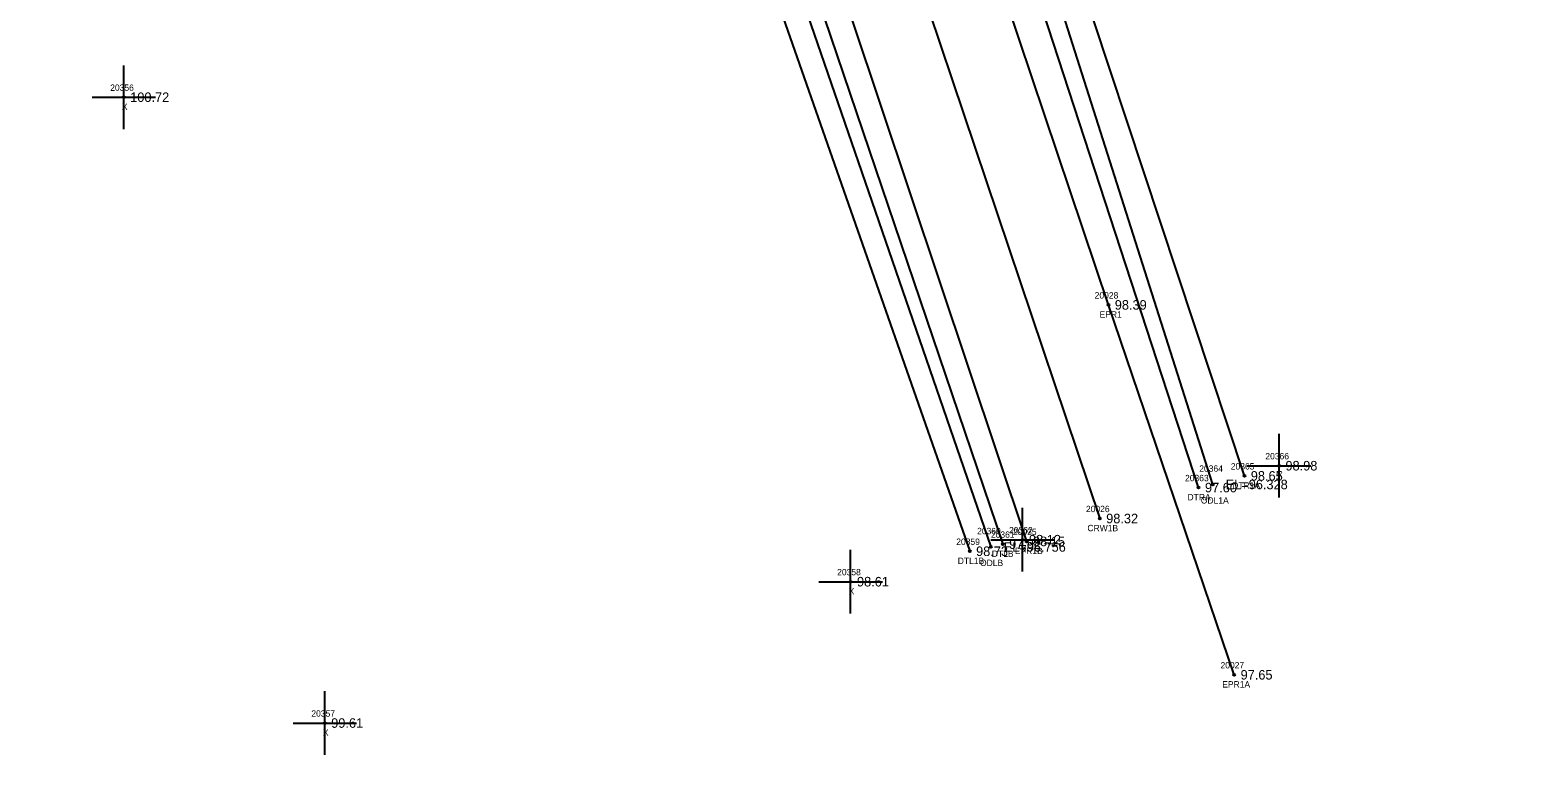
# Model space of a CAD drawing. Extents: x 2530197 to 2532051, y 935230 to 936631.
# Drawn here: x 2530401.9 to 2530638.9, y 935229.9 to 935343.8 of the extents above; entities that cross this region are included whole.
import ezdxf

# ---------------------------------------------------------------- set-up
doc = ezdxf.new("R2010")
doc.units = 0
for name, color, linetype in [('RD_DTM_BkLn1', 7, 'Continuous'), ('RD_EX_H2O', 7, 'Continuous'), ('RD_EX_H2O_txCode', 7, 'Continuous'), ('RD_EX_Misc', 7, 'Continuous'), ('RD_EX_Misc_txCode', 7, 'Continuous'), ('RD_EX_Road', 7, 'Continuous'), ('RD_EX_Road_txCode', 7, 'Continuous'), ('RD_EX_TX_H2O_ELEV', 7, 'Continuous'), ('RD_EX_TX_Misc_ELEV', 7, 'Continuous'), ('RD_EX_TX_Road_ELEV', 7, 'Continuous'), ('RD_HC_Survey_ELEV', 7, 'Continuous'), ('RD_HC_Survey_txCode', 7, 'Continuous'), ('RD_SMD_Locator', 7, 'Continuous')]:
    doc.layers.add(name, color=color, linetype=linetype)

msp = doc.modelspace()

# ---------------------------------------------------------------- linework, layer by layer
at = {"layer": 'RD_DTM_BkLn1'}
msp.add_lwpolyline([(2530465.37, 935579.66), (2530474.48, 935552.87), (2530506.43, 935456.79), (2530537.92, 935362.65), (2530570.08, 935267.03)], dxfattribs=at)
at = {"layer": 'RD_EX_H2O'}
for points in [[(2530585.61, 935271.89), (2530554.63, 935366.84), (2530523, 935462.44), (2530497.71, 935534.53), (2530497.63, 935550.35), (2530501.9, 935567.07), (2530512.76, 935580.06), (2530532.29, 935593.54), (2530580.75, 935621.41), (2530622.78, 935645.99), (2530706.38, 935694.8)], [(2530592.81, 935273.73), (2530561.2, 935369.39), (2530529.39, 935464.13), (2530504.24, 935535.46), (2530502.94, 935549.83), (2530506.75, 935563.82), (2530516.63, 935575.2), (2530535.16, 935588.8), (2530583.24, 935617.5), (2530624.86, 935641.7), (2530708.31, 935690.59), (2530708.33, 935693.17), (2530706.38, 935694.8)], [(2530587.86, 935272.38), (2530557.35, 935368.29), (2530525.38, 935463.03), (2530500.38, 935535.14), (2530499.61, 935550.4), (2530504.44, 935565.67), (2530514.36, 935577.87), (2530533.45, 935591.79), (2530582.01, 935619.78), (2530623.26, 935643.67), (2530705.7, 935692.18)], [(2530212.43, 935575.3), (2530312.61, 935575.57), (2530413.4, 935574.03), (2530431.14, 935570.94), (2530447.74, 935563.43), (2530459.72, 935547.88), (2530491.74, 935452.52), (2530522.77, 935357.57), (2530554.82, 935263)], [(2530212.28, 935572.05), (2530311.96, 935572.07), (2530413.48, 935570.72), (2530429.97, 935567.74), (2530445.97, 935560.86), (2530457.18, 935547.13), (2530489.52, 935451.8), (2530520.38, 935357.21), (2530552.97, 935262.56)], [(2530212.78, 935569.06), (2530311.54, 935568.98), (2530412.57, 935565.49), (2530428.32, 935562.93), (2530442.59, 935555.84), (2530453.4, 935544.85), (2530485.1, 935450.23), (2530516.56, 935356.42), (2530549.63, 935261.88)]]:
    msp.add_lwpolyline(points, dxfattribs=at)
at = {"layer": 'RD_EX_Misc'}
for p, q in [((2530416.66, 935328.26), (2530416.66, 935338.26)), ((2530411.66, 935333.26), (2530421.66, 935333.26)), ((2530598.26, 935270.33), (2530598.26, 935280.33)), ((2530593.26, 935275.33), (2530603.26, 935275.33)), ((2530557.95, 935258.7), (2530557.95, 935268.7)), ((2530552.95, 935263.7), (2530562.95, 935263.7)), ((2530530.91, 935252.1), (2530530.91, 935262.1)), ((2530525.91, 935257.1), (2530535.91, 935257.1)), ((2530448.26, 935229.88), (2530448.26, 935239.88)), ((2530443.26, 935234.88), (2530453.26, 935234.88))]:
    msp.add_line(p, q, dxfattribs=at)
at = {"layer": 'RD_EX_Road'}
for points in [[(2530591.21, 935242.46), (2530571.43, 935300.61), (2530549.4, 935366.29), (2530518.07, 935460.9), (2530493.7, 935533.55), (2530494.46, 935557.42), (2530501.12, 935573.63), (2530518.05, 935590.5), (2530533.43, 935598.45)], [(2530402.98, 935580.64), (2530413.62, 935578.66), (2530430.98, 935574.56), (2530444.41, 935568.86), (2530451.97, 935562.31), (2530461.09, 935548.32), (2530494.98, 935453.81), (2530526.54, 935359.14), (2530558.58, 935263.43)]]:
    msp.add_lwpolyline(points, dxfattribs=at)
at = {"layer": 'RD_SMD_Locator'}
for centre in [(2530416.66, 935333.26), (2530571.43, 935300.61), (2530598.26, 935275.33), (2530592.81, 935273.73), (2530585.61, 935271.89), (2530587.86, 935272.38), (2530570.08, 935267.03), (2530554.82, 935263), (2530557.95, 935263.7), (2530558.58, 935263.43), (2530549.63, 935261.88), (2530552.97, 935262.56), (2530530.91, 935257.1), (2530591.21, 935242.46), (2530448.26, 935234.88)]:
    msp.add_circle(centre, 0.15, dxfattribs=at)

# ---------------------------------------------------------------- texts
at = {"layer": 'RD_EX_H2O_txCode'}
for s, p in [('20364', (2530585.71, 935274.38)), ('20365', (2530590.67, 935274.73)), ('20363', (2530583.47, 935272.89)), ('DTR1A', (2530590.89, 935271.73)), ('DTRA', (2530583.86, 935269.89)), ('ODL1A', (2530585.96, 935269.38)), ('20360', (2530550.79, 935264.56)), ('20359', (2530547.51, 935262.88)), ('20361', (2530552.96, 935264)), ('DTL1B', (2530547.75, 935259.88)), ('DTLB', (2530553.1, 935261)), ('ODLB', (2530551.25, 935259.56))]:
    msp.add_text(s, height=1, dxfattribs=at).set_placement(p)
at = {"layer": 'RD_EX_Misc_txCode'}
for s, p in [('20356', (2530414.52, 935334.26)), ('X', (2530416.35, 935331.26)), ('20366', (2530596.1, 935276.33)), ('X', (2530597.95, 935273.33)), ('20362', (2530555.81, 935264.7)), ('X', (2530557.63, 935261.7)), ('20358', (2530528.79, 935258.1)), ('X', (2530530.6, 935255.1)), ('20357', (2530446.14, 935235.88)), ('X', (2530447.95, 935232.88))]:
    msp.add_text(s, height=1, dxfattribs=at).set_placement(p)
at = {"layer": 'RD_EX_Road_txCode'}
for s, p in [('20028', (2530569.27, 935301.61)), ('EPR1', (2530570.04, 935298.61)), ('20025', (2530556.42, 935264.43)), ('EPR1B', (2530556.72, 935261.43)), ('20027', (2530589.05, 935243.46)), ('EPR1A', (2530589.32, 935240.46))]:
    msp.add_text(s, height=1, dxfattribs=at).set_placement(p)
at = {"layer": 'RD_EX_TX_H2O_ELEV'}
for s, p in [('97.60', (2530586.61, 935271.14)), ('EL=96.328', (2530589.86, 935271.63)), ('98.65', (2530593.81, 935272.98)), ('EL=96.756', (2530554.97, 935261.81)), ('97.92', (2530555.82, 935262.25)), ('98.73', (2530550.63, 935261.13))]:
    msp.add_text(s, height=1.5, dxfattribs=at).set_placement(p)
at = {"layer": 'RD_EX_TX_Misc_ELEV'}
for s, p in [('100.72', (2530417.66, 935332.51)), ('98.98', (2530599.26, 935274.58)), ('98.12', (2530558.95, 935262.95)), ('98.61', (2530531.91, 935256.35)), ('99.61', (2530449.26, 935234.13))]:
    msp.add_text(s, height=1.5, dxfattribs=at).set_placement(p)
at = {"layer": 'RD_EX_TX_Road_ELEV'}
for s, p in [('98.39', (2530572.43, 935299.86)), ('98.15', (2530559.58, 935262.68)), ('97.65', (2530592.21, 935241.71))]:
    msp.add_text(s, height=1.5, dxfattribs=at).set_placement(p)
at = {"layer": 'RD_HC_Survey_ELEV'}
msp.add_text('98.32', height=1.5, dxfattribs=at).set_placement((2530571.08, 935266.28))
at = {"layer": 'RD_HC_Survey_txCode'}
for s, p in [('20026', (2530567.9, 935268.03)), ('CRW1B', (2530568.13, 935265.03))]:
    msp.add_text(s, height=1, dxfattribs=at).set_placement(p)

doc.saveas('drawing.dxf')
